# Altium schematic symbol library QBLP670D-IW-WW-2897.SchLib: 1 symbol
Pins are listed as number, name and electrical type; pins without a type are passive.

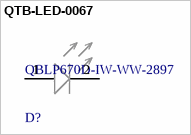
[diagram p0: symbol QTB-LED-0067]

## QTB-LED-0067
designator D?, comment QBLP670D-IW-WW-2897
LED WARM WHITE CLEAR 2PLCC SMD; Manufacturer: QT Brightek (QTB); Lens Size: 2.4mm; Luminous Intensity: 7500mcd; Test Current: 20mA; Lens Color: Colorless; Lens Style: Round with Domed Top; Forward Voltage: 2.8V; Viewing Angle: 30°
footprint QBLP670D-IW-WW-2897-MFG
pins: 1 ANODE (+), 2 CATHODE (-)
